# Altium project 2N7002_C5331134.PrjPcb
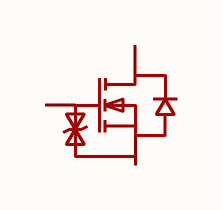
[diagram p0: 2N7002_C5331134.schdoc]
1 sheet, 1 parts. Net scope: global (net labels, ports and power ports of the same name join across sheets).

## Sheet 2N7002_C5331134.schdoc
size 127 x 101 mm

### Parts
Q?  2n7002_c5331134  [SOT-23-3_L2.9-W1.3-P0.95-LS2.4-BR]  (value not drawn)

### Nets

Not connected (* = marked no-connect by the designer): Q? 1(G) 2(S) 3(D)

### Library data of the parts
Q? = 2n7002_c5331134: 数量:1个N沟道;漏源电压(Vdss):60V;连续漏极电流(Id):300mA;导通电阻(RDS(on)):2.2Ω@10V;耗散功率(Pd):350mW;阈值电压(Vgs(th)):1.6V;; Manufacturer: MSKSEMI(美森科); ManufacturerPart: 2N7002; AddInBom: yes; ModelId: c62791f0466c4ae2a892c056b845b0ca; ModelName: SOT-23-3P_L2.9-W1.3-H1.0-LS2.4-P0.95; ModelTransform: 98.425,114.173,0,180,0,0,0.0005,-0.0005,0; Number: 1个N沟道; Drain to Source Voltage: 60V; Current - Continuous Drain(Id): 300mA; Pd - Power Dissipation: 350mW; Gate Threshold Voltage (Vgs(th)): 1.6V; Gate Charge(Qg): 5.6nC@10V; Input Capacitance(Ciss): 38pF; Reverse Transfer Capacitance (Crss@Vds): 12pF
